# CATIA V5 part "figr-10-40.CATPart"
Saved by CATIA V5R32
Part number: Part3
Bounding box of the stored display mesh (mm): x -57.458 to 20, y -85.932 to 127.979, z -59.826 to 86.386
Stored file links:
  D:\PROJECTS\Project 2022\CATIA V5 6R 2022\Resources\Part Files\c10_catia_v5_6r2022_prt\c10_catia_v5_6r2022_prt\figr-10-40.CATPart
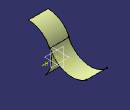
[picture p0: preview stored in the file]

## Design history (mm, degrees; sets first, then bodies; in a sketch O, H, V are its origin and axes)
Body1 (main body)
  Sketch1 on yz-plane, origin (0, 0, 0), H (0, 1, 0), V (0, 0, 1)
    arc A1 centre (-86.3872, 0) radius 86.3872 from (-24.0683, -59.8256) to (-85.9323, 86.386) ccw
    point P1 (-86.3872, 0)
    coincidence: A1 O, P1 H
  Extrude1: Element1 Sketch1, Lim1 20, Lim2 53
  Sketch2 on zx-plane, origin (0, 0, 0), H (-1, 0, 0), V (0, 0, 1)
    line L1 (-18.8028, 37.5161) -> (51.5353, 37.5161)
    horizontal: L1 H
  Project1: ToProject Sketch2, Support Extrude1
  Sketch3 on xy-plane, origin (0, 0, 0), H (1, 0, 0), V (0, 1, 0)
    line L1 (-57.4576, 127.9794) -> (17.5097, 127.9794)
    horizontal: L1 H
  Sweep1: type Circle, Guide (Project1; Sketch3), Reference Extrude1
